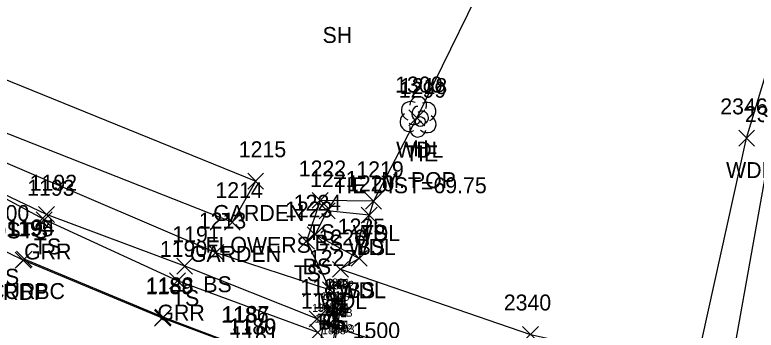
# Model space of a CAD drawing. Extents: x 1761340 to 1763889, y 696770 to 706023.
# Drawn here: x 1761564.7 to 1761657.7, y 700878.5 to 700918.1 of the extents above; entities that cross this region are included whole.
import ezdxf

# ---------------------------------------------------------------- set-up
doc = ezdxf.new("R2010")
doc.units = 0
for name, color, linetype in [('B_A', 7, 'Continuous'), ('B_I', 7, 'Continuous'), ('B_TIC', 7, 'Continuous'), ('BDC', 7, 'Continuous'), ('BF', 7, 'Continuous'), ('BSE', 7, 'Continuous'), ('BSUBM', 7, 'Continuous'), ('C_A', 7, 'Continuous'), ('C_C', 7, 'Continuous'), ('C_I', 7, 'Continuous'), ('CBP', 7, 'Continuous'), ('D_I', 7, 'Continuous'), ('L_A', 7, 'Continuous'), ('L_C', 7, 'Continuous'), ('L_I', 7, 'Continuous'), ('L_TIC', 7, 'Continuous'), ('LAPB', 7, 'Continuous'), ('LAWA', 7, 'Continuous'), ('LELB', 7, 'Continuous'), ('LTD', 7, 'Continuous'), ('P_A', 7, 'Continuous'), ('P_I', 7, 'Continuous'), ('P_TIC', 7, 'Continuous'), ('PET', 7, 'Continuous'), ('R_A', 7, 'Continuous'), ('R_C', 7, 'Continuous'), ('R_I', 7, 'Continuous'), ('R_TIC', 7, 'Continuous'), ('RC', 7, 'Continuous'), ('RGR', 7, 'Continuous')]:
    doc.layers.add(name, color=color, linetype=linetype)

msp = doc.modelspace()

# ---------------------------------------------------------------- linework, layer by layer
at = {"layer": 'B_TIC'}
for p, q in [((1761604.846, 700882.276), (1761604.921, 700882.276)), ((1761604.858, 700882.521), (1761604.934, 700882.521)), ((1761605.279, 700882.155), (1761605.354, 700882.155)), ((1761605.672, 700882.23), (1761605.747, 700882.23)), ((1761604.5, 700880.832), (1761604.575, 700880.832)), ((1761605.068, 700880.725), (1761605.144, 700880.725)), ((1761603.375, 700879.329), (1761603.451, 700879.329)), ((1761603.375, 700879.329), (1761603.451, 700879.329)), ((1761604, 700879.477), (1761604.076, 700879.477)), ((1761604.886, 700879.181), (1761604.961, 700879.181)), ((1761604.973, 700879.202), (1761605.049, 700879.202))]:
    msp.add_line(p, q, dxfattribs=at)
for points in [[(1761604.842, 700881.776), (1761604.842, 700882.776)], [(1761604.855, 700882.021), (1761604.855, 700883.021)], [(1761605.275, 700881.655), (1761605.275, 700882.655)], [(1761605.668, 700881.73), (1761605.668, 700882.73)], [(1761604.342, 700882.276), (1761605.342, 700882.276)], [(1761604.355, 700882.521), (1761605.355, 700882.521)], [(1761604.775, 700882.155), (1761605.775, 700882.155)], [(1761605.168, 700882.23), (1761606.168, 700882.23)], [(1761603.996, 700880.832), (1761604.996, 700880.832)], [(1761604.496, 700880.332), (1761604.496, 700881.332)], [(1761604.565, 700880.725), (1761605.565, 700880.725)], [(1761605.065, 700880.225), (1761605.065, 700881.225)], [(1761603.372, 700878.829), (1761603.372, 700879.829)], [(1761603.372, 700878.829), (1761603.372, 700879.829)], [(1761603.997, 700878.977), (1761603.997, 700879.977)], [(1761602.872, 700879.329), (1761603.872, 700879.329)], [(1761602.872, 700879.329), (1761603.872, 700879.329)], [(1761603.497, 700879.477), (1761604.497, 700879.477)], [(1761604.382, 700879.181), (1761605.382, 700879.181)], [(1761604.47, 700879.202), (1761605.47, 700879.202)], [(1761604.882, 700878.681), (1761604.882, 700879.681)], [(1761604.97, 700878.702), (1761604.97, 700879.702)]]:
    msp.add_lwpolyline(points, dxfattribs=at)
at = {"layer": 'BDC'}
msp.add_lwpolyline([(1761603.372, 700879.329), (1761602.459, 700873.228), (1761625.807, 700865.915), (1761643.998, 700861.743), (1761666.42, 700857.506), (1761686.349, 700855.322), (1761703.242, 700853.873), (1761720.711, 700853.034), (1761728.973, 700853.355), (1761729.967, 700859.215)], dxfattribs=at)
at = {"layer": 'BF'}
msp.add_lwpolyline([(1761603.372, 700879.329), (1761627.262, 700871.889), (1761644.624, 700867.82), (1761667.288, 700863.505), (1761686.862, 700861.108), (1761704.425, 700859.764), (1761721.12, 700859.13), (1761729.967, 700859.215)], dxfattribs=at)
at = {"layer": 'BSE'}
msp.add_lwpolyline([(1761604.97, 700879.202), (1761603.208, 700869.221), (1761603.206, 700869.184), (1761602.269, 700863.396), (1761602.227, 700863.351), (1761601.457, 700858.276), (1761601.422, 700858.259), (1761600.545, 700852.441), (1761600.535, 700852.421), (1761599.823, 700846.766)], dxfattribs=at)
at = {"layer": 'BSUBM'}
for points in [[(1761604.855, 700882.521), (1761605.668, 700882.23), (1761604.826, 700877.221), (1761602.145, 700861.187), (1761601.761, 700856.927), (1761600.323, 700849.766)], [(1761604.842, 700882.276), (1761605.275, 700882.155), (1761605.065, 700880.725), (1761604.882, 700879.181), (1761603.997, 700879.477), (1761604.496, 700880.832)]]:
    msp.add_lwpolyline(points, dxfattribs=at)
at = {"layer": 'CBP'}
for radius in [0.625, 0.0833]:
    msp.add_circle((1761615.565, 700904.731), radius, dxfattribs=at)
at = {"layer": 'L_TIC'}
for points in [[(1761614.117, 700904.197), (1761616.117, 700906.197)], [(1761616.117, 700904.197), (1761614.117, 700906.197)], [(1761655.53, 700901.641), (1761657.53, 700903.641)], [(1761657.53, 700901.641), (1761655.53, 700903.641)], [(1761593.896, 700896.253), (1761595.896, 700898.253)], [(1761595.896, 700896.253), (1761593.896, 700898.253)], [(1761593.896, 700896.253), (1761595.896, 700898.253)], [(1761595.896, 700896.253), (1761593.896, 700898.253)], [(1761601.997, 700893.841), (1761603.997, 700895.841)], [(1761603.997, 700893.841), (1761601.997, 700895.841)], [(1761608.669, 700893.734), (1761610.669, 700895.734)], [(1761610.669, 700893.734), (1761608.669, 700895.734)], [(1761608.669, 700893.734), (1761610.669, 700895.734)], [(1761610.669, 700893.734), (1761608.669, 700895.734)], [(1761567.649, 700892.055), (1761569.649, 700894.055)], [(1761569.649, 700892.055), (1761567.649, 700894.055)], [(1761602.855, 700892.528), (1761604.855, 700894.528)], [(1761604.855, 700892.528), (1761602.855, 700894.528)], [(1761608.132, 700891.975), (1761610.132, 700893.975)], [(1761610.132, 700891.975), (1761608.132, 700893.975)], [(1761608.132, 700891.975), (1761610.132, 700893.975)], [(1761610.132, 700891.975), (1761608.132, 700893.975)], [(1761590.965, 700891.115), (1761592.965, 700893.115)], [(1761592.965, 700891.115), (1761590.965, 700893.115)], [(1761601.362, 700889.533), (1761603.362, 700891.533)], [(1761603.362, 700889.533), (1761601.362, 700891.533)], [(1761600.262, 700888.693), (1761602.262, 700890.693)], [(1761602.262, 700888.693), (1761600.262, 700890.693)], [(1761588.878, 700887.3), (1761590.878, 700889.3)], [(1761590.878, 700887.3), (1761588.878, 700889.3)], [(1761606.884, 700886.554), (1761608.884, 700888.554)], [(1761608.884, 700886.554), (1761606.884, 700888.554)], [(1761606.884, 700886.554), (1761608.884, 700888.554)], [(1761608.884, 700886.554), (1761606.884, 700888.554)], [(1761584.982, 700885.583), (1761586.982, 700887.583)], [(1761586.982, 700885.583), (1761584.982, 700887.583)], [(1761604.527, 700885.179), (1761606.527, 700887.179)], [(1761606.527, 700885.179), (1761604.527, 700887.179)], [(1761603.264, 700882.606), (1761605.264, 700884.606)], [(1761605.264, 700882.606), (1761603.264, 700884.606)], [(1761603.264, 700882.606), (1761605.264, 700884.606)], [(1761605.264, 700882.606), (1761603.264, 700884.606)], [(1761601.619, 700878.961), (1761603.619, 700880.961)], [(1761603.619, 700878.961), (1761601.619, 700880.961)], [(1761628.386, 700877.008), (1761630.386, 700879.008)], [(1761630.386, 700877.008), (1761628.386, 700879.008)]]:
    msp.add_lwpolyline(points, dxfattribs=at)
at = {"layer": 'LAPB'}
for points in [[(1761558.728, 700911.937), (1761555.319, 700906.539), (1761591.965, 700892.115), (1761594.896, 700897.253)], [(1761558.728, 700911.937), (1761594.896, 700897.253)]]:
    msp.add_lwpolyline(points, dxfattribs=at)
at = {"layer": 'LAWA'}
for points in [[(1761656.53, 700902.641), (1761667.453, 700938.832)], [(1761625.698, 700926.846), (1761615.117, 700905.197), (1761609.669, 700894.734), (1761609.132, 700892.975), (1761607.884, 700887.554), (1761605.527, 700886.179)], [(1761629.386, 700878.008), (1761650.052, 700873.461), (1761656.53, 700902.641)], [(1761605.527, 700886.179), (1761629.386, 700878.008)]]:
    msp.add_lwpolyline(points, dxfattribs=at)
at = {"layer": 'LELB'}
for points in [[(1761647.361, 700568.693), (1761651.507, 700589.637), (1761652.179, 700611.172), (1761648.147, 700645.92), (1761644.284, 700683.035), (1761641.556, 700721.375), (1761643.749, 700763.66), (1761644.587, 700792.445), (1761648.472, 700827.402), (1761652.737, 700863.508), (1761659.58, 700901.674), (1761670.104, 700938.531), (1761679.505, 700964.488), (1761691.194, 701008.19), (1761682.174, 701016.504)], [(1761602.619, 700879.961), (1761585.982, 700886.583), (1761568.649, 700893.055), (1761556.016, 700899.061), (1761541.394, 700907.299), (1761538.027, 700904.954), (1761552.404, 700894.699), (1761563.376, 700889.246)], [(1761550.158, 700903.642), (1761557.099, 700902.306), (1761589.878, 700888.3), (1761604.264, 700883.606)], [(1761609.669, 700894.734), (1761602.997, 700894.841), (1761601.262, 700889.693), (1761604.264, 700883.606)], [(1761609.132, 700892.975), (1761603.855, 700893.528), (1761602.362, 700890.533), (1761607.884, 700887.554)]]:
    msp.add_lwpolyline(points, dxfattribs=at)
at = {"layer": 'LTD'}
msp.add_line((1761615.26, 700905.383), (1761615.26, 700905.383), dxfattribs=at)
msp.add_line((1761615.26, 700905.383), (1761615.26, 700905.383), dxfattribs=at)
msp.add_arc((1761615.307, 700906.817), 1.047, 335.52715, 180.95627, dxfattribs=at)
for centre, major_axis, ratio, start_param, end_param in [((1761614.468, 700906.049), (1.21, -0.512), 0.895232, 1.570796, 4.712389), ((1761616.302, 700905.966), (-1.141, -0.483), 0.949671, 1.570796, 4.712389), ((1761615.052, 700905.841), (-0.208, -0.792), 0.645439, 3.141593, 6.283185), ((1761615.76, 700905.216), (-0.5, 0.667), 0.989748, 3.141593, 6.283185), ((1761614.177, 700904.674), (0.584, -1.042), 0.959034, 3.141593, 6.283185), ((1761616.26, 700904.55), (-1.09, 0.792), 0.841452, 1.570796, 4.712389), ((1761615.261, 700903.883), (0.265, 1.061), 0.942809, 1.570796, 4.712389), ((1761614.802, 700904.633), (-0.625, -0.083), 0.423636, 0, 3.141593)]:
    msp.add_ellipse(centre, major_axis=major_axis, ratio=ratio, start_param=start_param, end_param=end_param, dxfattribs=at)
at = {"layer": 'P_TIC'}
for points in [[(1761564.694, 700886.32), (1761566.694, 700888.32)], [(1761566.694, 700886.32), (1761564.694, 700888.32)], [(1761582.21, 700879.042), (1761584.21, 700881.042)], [(1761584.21, 700879.042), (1761582.21, 700881.042)]]:
    msp.add_lwpolyline(points, dxfattribs=at)
at = {"layer": 'PET'}
msp.add_lwpolyline([(1761551.015, 700866.825), (1761575.841, 700857.112), (1761588.612, 700852.655), (1761598.439, 700849.106), (1761600.688, 700862.06), (1761602.26, 700873.054), (1761592.745, 700876.48), (1761583.21, 700880.042), (1761565.694, 700887.32), (1761551.927, 700894.01)], dxfattribs=at)
at = {"layer": 'R_TIC'}
for points in [[(1761567.333, 700891.416), (1761569.333, 700893.416)], [(1761569.333, 700891.416), (1761567.333, 700893.416)], [(1761564.849, 700886.443), (1761566.849, 700888.443)], [(1761566.849, 700886.443), (1761564.849, 700888.443)], [(1761584.074, 700883.738), (1761586.074, 700885.738)], [(1761586.074, 700883.738), (1761584.074, 700885.738)], [(1761582.275, 700879.167), (1761584.275, 700881.167)], [(1761584.275, 700879.167), (1761582.275, 700881.167)], [(1761601.711, 700877.245), (1761603.711, 700879.245)], [(1761603.711, 700877.245), (1761601.711, 700879.245)]]:
    msp.add_lwpolyline(points, dxfattribs=at)
at = {"layer": 'RC'}
msp.add_lwpolyline([(1761602.258, 700873.311), (1761592.794, 700876.572), (1761583.275, 700880.167), (1761565.849, 700887.443)], dxfattribs=at)
at = {"layer": 'RGR'}
msp.add_lwpolyline([(1761602.711, 700878.245), (1761585.074, 700884.738), (1761568.333, 700892.416), (1761556.016, 700899.061)], dxfattribs=at)

# ---------------------------------------------------------------- texts
at = {"layer": 'B_A'}
for s, p in [('XAT', (1761603.547, 700880.276)), ('XAB', (1761603.575, 700880.521)), ('XAT', (1761603.98, 700880.155)), ('XAB', (1761604.389, 700880.23)), ('XAT', (1761603.201, 700878.832)), ('XAT', (1761603.77, 700878.725))]:
    msp.add_text(s, height=1, dxfattribs=at).set_placement(p)
at = {"layer": 'B_I'}
for s, p in [('1303', (1761603.457, 700883.776)), ('1301', (1761603.753, 700884.021)), ('1304', (1761603.89, 700883.655)), ('1302', (1761604.282, 700883.73)), ('1308', (1761603.11, 700882.332)), ('1305', (1761603.679, 700882.225)), ('1309', (1761601.982, 700880.829)), ('1309', (1761601.982, 700880.829)), ('1307', (1761602.611, 700880.977)), ('1306', (1761603.469, 700880.681)), ('1843', (1761603.623, 700880.702)), ('1310', (1761602.297, 700879.477)), ('1858', (1761603.229, 700878.02)), ('1501', (1761603.724, 700878.721)), ('1502', (1761604.108, 700878.284)), ('1503', (1761604.319, 700878.173))]:
    msp.add_text(s, height=1, dxfattribs=at).set_placement(p)
at = {"layer": 'C_A'}
msp.add_text('TIE', height=2, dxfattribs=at).set_placement((1761613.644, 700899.731))
at = {"layer": 'C_C'}
msp.add_text('TIE DIST=69.75', height=2, dxfattribs=at).set_placement((1761604.652, 700895.731))
at = {"layer": 'C_I'}
msp.add_text('1299', height=2, dxfattribs=at).set_placement((1761612.865, 700907.731))
at = {"layer": 'D_I'}
for s, p in [('1180', (1761591.501, 700877.99)), ('1179', (1761591.555, 700878.009)), ('1181', (1761591.822, 700877.024))]:
    msp.add_text(s, height=2, dxfattribs=at).set_placement(p)
at = {"layer": 'L_A'}
for s, p in [('SH', (1761603.291, 700914.607)), ('WDL', (1761612.534, 700900.197)), ('H', (1761614.693, 700900.383)), ('WDL', (1761653.948, 700897.641)), ('GARDEN', (1761589.566, 700892.253)), ('GARDEN', (1761589.566, 700892.253)), ('TS', (1761601.406, 700889.841)), ('WDL', (1761607.086, 700889.734)), ('TS', (1761608.078, 700889.734)), ('TS', (1761567.058, 700888.055)), ('BS', (1761602.296, 700888.528)), ('BS', (1761607.573, 700887.975)), ('GARDEN', (1761586.635, 700887.115)), ('WDL', (1761606.55, 700887.975)), ('BS', (1761600.803, 700885.533)), ('TS', (1761599.671, 700884.693)), ('TS', (1761561.786, 700884.246)), ('BS', (1761588.319, 700883.3)), ('WDL', (1761605.302, 700882.554)), ('BS', (1761606.325, 700882.554)), ('TS', (1761584.392, 700881.583)), ('WDL', (1761602.945, 700881.179)), ('TS', (1761602.674, 700878.606)), ('BS', (1761602.705, 700878.606))]:
    msp.add_text(s, height=2, dxfattribs=at).set_placement(p)
at = {"layer": 'L_C'}
for s, p in [('M. POP', (1761610.67, 700896.383)), ('FLOWERS', (1761588.597, 700888.253)), ('FLOWERS', (1761588.597, 700888.253))]:
    msp.add_text(s, height=2, dxfattribs=at).set_placement(p)
at = {"layer": 'L_I'}
for s, p in [('1300', (1761612.402, 700908.383)), ('1218', (1761612.991, 700908.197)), ('2346', (1761653.216, 700905.641)), ('2347', (1761656.321, 700904.674)), ('1215', (1761592.771, 700900.253)), ('1215', (1761592.771, 700900.253)), ('1222', (1761600.304, 700897.841)), ('1219', (1761607.535, 700897.734)), ('1219', (1761607.535, 700897.734)), ('1221', (1761601.73, 700896.528)), ('1192', (1761566.523, 700896.055)), ('1220', (1761606.353, 700895.975)), ('1220', (1761606.353, 700895.975)), ('1214', (1761589.84, 700895.115)), ('1223', (1761598.569, 700892.693)), ('1224', (1761599.67, 700893.533)), ('1200', (1761560.518, 700892.246)), ('1213', (1761587.753, 700891.3)), ('1225', (1761605.192, 700890.554)), ('1225', (1761605.192, 700890.554)), ('1191', (1761584.423, 700889.583)), ('1226', (1761602.779, 700889.179)), ('1227', (1761601.572, 700886.606)), ('1227', (1761601.572, 700886.606)), ('1185', (1761600.493, 700882.961)), ('2340', (1761626.04, 700881.008)), ('1500', (1761607.072, 700877.514))]:
    msp.add_text(s, height=2, dxfattribs=at).set_placement(p)
at = {"layer": 'P_A'}
msp.add_text('RDP', height=2, dxfattribs=at).set_placement((1761563.182, 700882.32))
at = {"layer": 'P_I'}
for s, p in [('1195', (1761563.569, 700890.32)), ('1189', (1761581.076, 700883.042)), ('1186', (1761590.565, 700879.48))]:
    msp.add_text(s, height=2, dxfattribs=at).set_placement(p)
at = {"layer": 'R_A'}
for s, p in [('GRR', (1761565.821, 700887.416)), ('CURBC', (1761561.432, 700882.443)), ('GRR', (1761582.562, 700879.738))]:
    msp.add_text(s, height=2, dxfattribs=at).set_placement(p)
at = {"layer": 'R_C'}
msp.add_text('SGR W/ WOOD POSTS', height=2, dxfattribs=at).set_placement((1761539.843, 700890.061))
at = {"layer": 'R_I'}
for s, p in [('1193', (1761566.207, 700895.416)), ('1194', (1761563.724, 700890.443)), ('1190', (1761582.861, 700887.738)), ('1188', (1761581.149, 700883.167)), ('1184', (1761600.586, 700881.245)), ('1187', (1761590.668, 700879.572))]:
    msp.add_text(s, height=2, dxfattribs=at).set_placement(p)

doc.saveas('drawing.dxf')
